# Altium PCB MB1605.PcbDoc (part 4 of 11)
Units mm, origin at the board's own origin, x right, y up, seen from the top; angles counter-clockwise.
Board outline 100 x 79.6 mm, 6 copper layers (Top Layer, Signal Layer 1, Signal Layer 2, Signal Layer 3, Signal Layer 4, Bottom Layer), stack 1.549 mm thick; 644 components, 529 nets, 2853 pads, 1462 vias.
Unrouted connection lines stored in the file: 2.
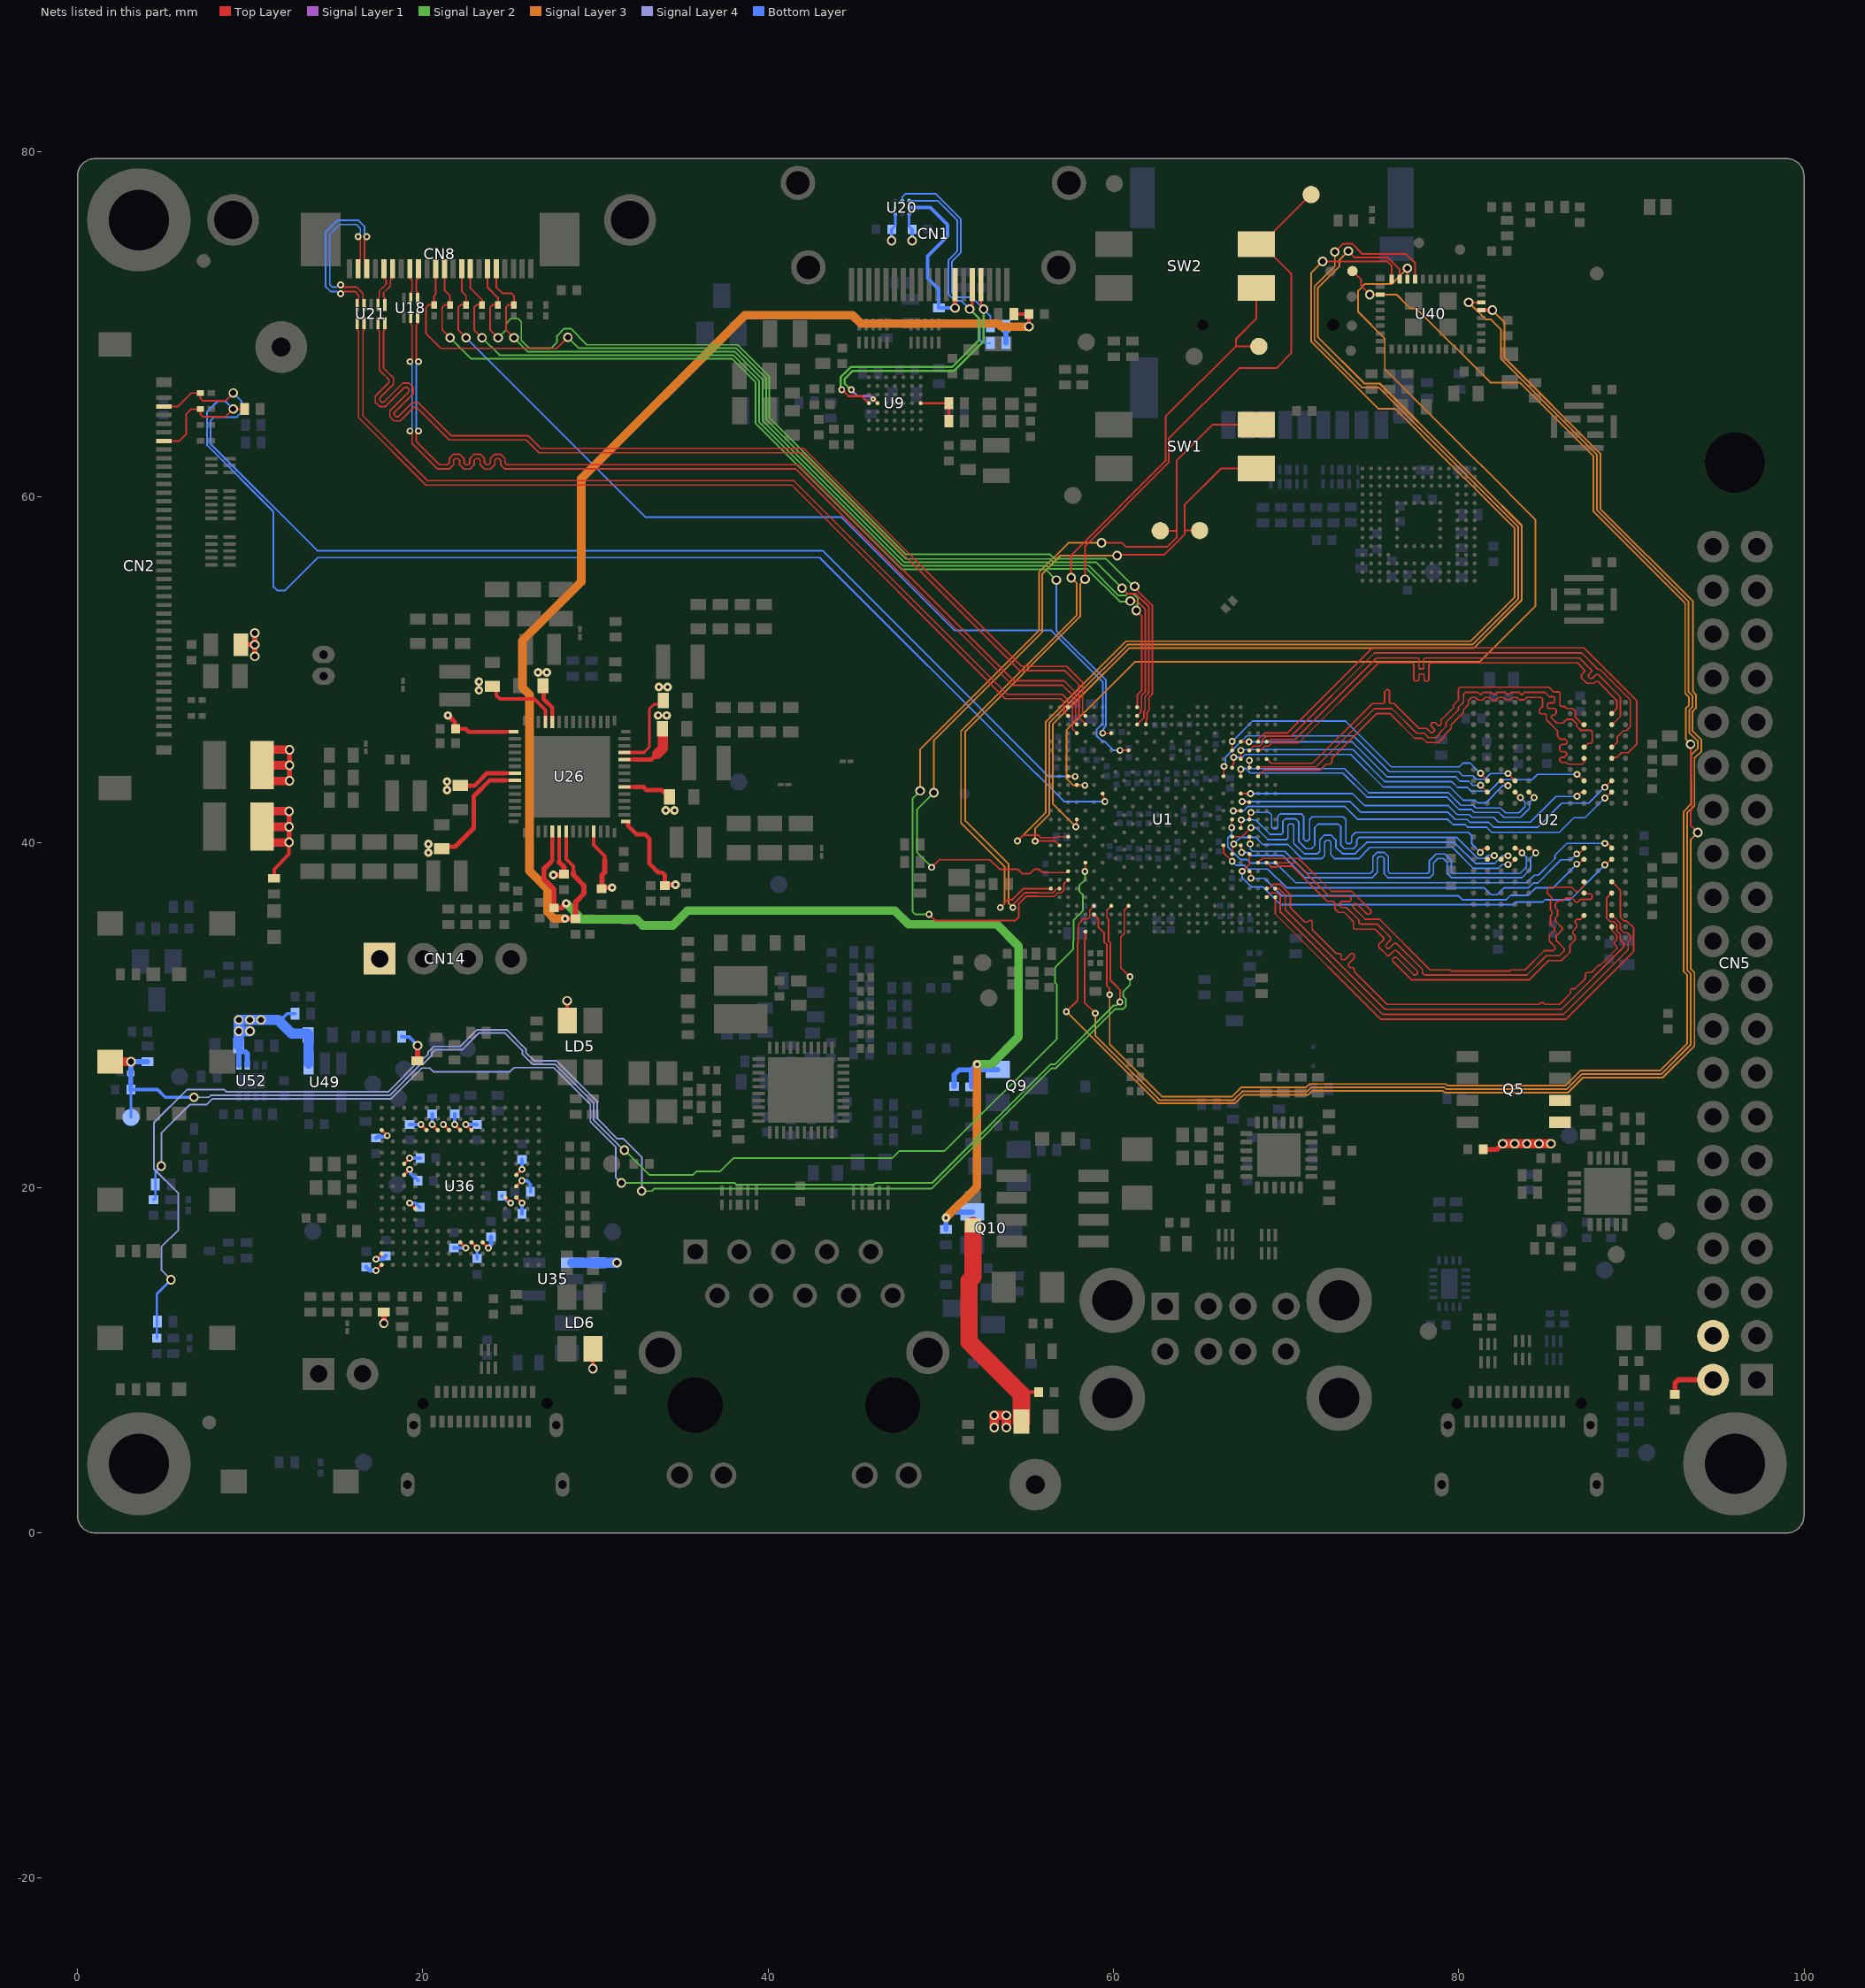
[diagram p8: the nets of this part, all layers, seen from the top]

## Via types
v1: diameter 0.55, hole 0.35, Top Layer to Bottom Layer, 823 vias
v2: diameter 0.4, hole 0.2, Top Layer to Bottom Layer, 235 vias
v3: diameter 0.4, hole 0.2, Top Layer to Bottom Layer, tented both sides, 216 vias
v4: diameter 0.5, hole 0.2, Top Layer to Bottom Layer, 159 vias
v5: diameter 0.25/0.3 (per signal layer), hole 0.1, Top Layer to Signal Layer 1, tented both sides, 29 vias

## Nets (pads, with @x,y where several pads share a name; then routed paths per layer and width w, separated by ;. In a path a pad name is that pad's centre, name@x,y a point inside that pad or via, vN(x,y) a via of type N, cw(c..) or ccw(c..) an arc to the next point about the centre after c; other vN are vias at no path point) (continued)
3V3_STLK: C129.2 C281.1 C282.1 C289.1 C290.1 C297.1 C298.1 C299.1 C303.1 C310.1 C311.1 C324.1 C325.1 C326.1 C327.1 C328.1 C329.1 C333.1 CN14.1 LD5.4 LD6.4 R156.2 R227.1 U35.1 U36.C1 U36.C5 U36.C6 U36.C7 U36.C8 U36.C9 U36.F3 U36.G3 U36.G13 U36.H13 U36.J12 U36.J13 U36.K4 U36.N8 U36.N9 U36.N10 U36.P1 U36.R1 | length 26.9
  Top Layer w0.15: v3(17.29,15.207) U36.R1@17.615,15.532 ; v3(17.29,15.857) U36.P1@17.615,16.182 ; U36.C1@17.615,23.332 v3(17.94,23.007) ; U36.G3@18.915,20.732 v3(19.24,21.057) ; U36.F3@18.915,21.382 v3(19.24,21.707) ; v3(19.24,19.107) U36.K4@19.565,18.782 ; v3(19.89,23.657) U36.C5@20.215,23.332 ; v3(20.54,23.657) U36.C6@20.865,23.332 ; v3(21.19,23.657) U36.C7@21.515,23.332 ; v3(21.84,23.657) U36.C8@22.165,23.332 ; U36.N8@22.165,16.832 v3(22.49,16.507) ; v3(22.49,23.657) U36.C9@22.815,23.332 ; U36.N9@22.815,16.832 v3(23.14,16.507) ; U36.N10@23.465,16.832 v3(23.79,16.507) ; U36.J12@24.765,19.432 v3(25.09,19.107) ; U36.J13@25.415,19.432 v3(25.74,19.107) ; U36.H13@25.415,20.082 v3(25.74,20.407) ; U36.G13@25.415,20.732 v3(25.74,21.057)
  Top Layer w0.2: LD5.4@28.358,29.675 v1(28.358,30.825) ; v1(29.85,9.519) LD6.4@29.85,10.669
  Top Layer w0.3: R156.2@19.69,27.357 19.69,28.215 v1(19.7,28.225)
  Bottom Layer w0.2: R227.1@18.765,28.75 18.792,28.722 19.203,28.722 v1(19.7,28.225) ; v3(19.24,19.107) 19.565,19.107 C299.1@19.815,18.857 ; v3(19.24,21.057) 19.278,21.019 19.278,20.844 19.535,20.587 19.56,20.587 19.715,20.432 C298.1@19.715,20.407 ; v3(19.24,21.707) C310.1@19.84,21.707 ; C289.1@19.24,23.657 v3(19.89,23.657) ; v3(20.54,23.657) C282.1@20.54,24.282 ; C326.1@21.79,16.507 v3(22.49,16.507) ; v3(21.84,23.657) C297.1@21.84,24.282 ; v3(22.49,23.657) C290.1@23.14,23.657 ; C325.1@23.14,15.882 v3(23.14,16.507) ; C329.1@24.59,19.532 24.59,19.507 24.745,19.352 24.77,19.352 24.977,19.145 25.052,19.145 v3(25.09,19.107) ; C303.1@25.74,18.482 v3(25.74,19.107) ; v3(25.74,20.407) 26.02,20.407 26.24,20.187 C328.1@26.24,19.757 ; v3(25.74,21.057) C311.1@25.74,21.632
  Bottom Layer w0.25: C327.1@16.715,15.407 16.915,15.207 v3(17.29,15.207) ; v3(17.29,15.857) 17.665,15.857 C281.1@17.865,16.057 ; C324.1@17.29,22.875 17.367,22.952 17.844,22.952 17.899,23.007 v3(17.94,23.007) ; v3(23.79,16.507) 23.945,16.662 C333.1@23.945,17.157
  Bottom Layer w0.6: U35.1@28.646,15.65 C129.2@30.17,15.65 v1(31.239,15.65)
5V_HDMI: C91.1 C179.2 R20.1 R21.2 R22.2 U26.7 | length 68.5
  Top Layer w0.2: R20.1@54.226,70.6 C179.2@55.103,70.6 ; v1(55.103,69.873) C179.2@55.103,70.6
  Top Layer w0.21: U26.7@28.3,40.63 28.3,39.025 28.715,38.61 28.715,38.253
  Top Layer w0.3: v4(28.24,35.58) C91.1@28.85,35.58 ; 28.715,38.253 28.715,38.118 29.335,37.498 29.335,37.035 28.85,36.55 C91.1@28.85,35.73
  Signal Layer 3 w0.5: v4(28.24,35.58) 27.619,35.58 27.223,35.976 27.223,37.302 26.175,38.35 26.175,48.553 25.769,48.959 25.769,51.68 29.175,55.086 29.175,61.065 38.645,70.534 44.893,70.534 45.378,70.049 53.326,70.049 53.502,69.873 v1(55.103,69.873)
  Bottom Layer w0.3: R22.2@53.776,68.92 R21.2@53.776,69.903 54.424,69.903 54.454,69.873 v1(55.103,69.873)
5V_STLK: C29.2 C30.2 C32.2 C38.2 C39.2 C42.1 C56.2 C94.2 C143.2 C146.2 C147.1 C165.2 C169.2 C180.2 C181.2 C184.2 C188.2 C199.2 C209.2 C213.2 C233.2 CN5.2 CN5.4 L12.1 Q5.5 Q5.6 R4.2 R210.1 R216.2 R230.1 U20.A1 U20.C1 U26.6 U26.11 U26.15 U26.20 U26.24 U26.25 U26.38 U26.39 U26.43 U26.49 U26.50 U49.1 U52.5 U52.6 | length 101.6
  Top Layer w0.15: 32.8,45.2 33.125,45.525 33.125,47.731 33.388,47.994 33.819,47.994 C32.2@33.925,48.1
  Top Layer w0.2: R210.1@11.386,37.915 11.386,38.449 12.244,39.307 v1@12.244,39.994 ; 54.67,8.389 54.899,8.16 C146.2@55.659,8.16
  Top Layer w0.21: C29.2@24.025,49.05 24.262,48.813 24.262,48.513 24.475,48.3 26.464,48.3 27.1,47.664 U26.39@27.1,46.97 ; 24.775,43.6 U26.50@25.33,43.6 ; 24.775,44 U26.49@25.33,44 ; 24.775,46.4 U26.43@25.33,46.4 ; U26.38@27.5,46.97 27.5,47.525 ; 27.9,38.85 U26.6@27.9,40.63 ; U26.11@29.9,40.63 29.9,39.843 30.54,39.203 30.54,38.975 ; U26.15@31.67,41.2 U26.15@31.745,41.2 U26.15@31.785,41.2 ; U26.20@31.67,43.2 32.225,43.2 ; U26.24@31.67,44.8 32.225,44.8 ; U26.25@31.67,45.2 32.8,45.2
  Top Layer w0.25: C56.2@21.1,39.75 21.875,39.75 22.95,40.825 22.95,42.669 23.881,43.6 24.775,43.6 ; 21.695,47.125 21.699,47.125 21.845,46.979 21.845,46.685 C39.2@21.955,46.575 ; C39.2@22.005,46.575 22.475,46.575 22.65,46.4 24.775,46.4 ; C199.2@22.175,43.275 22.991,43.275 23.716,44 24.775,44 ; C30.2@26.925,49.075 26.994,49.006 26.994,48.308 27.5,47.802 27.5,47.525 ; 31.895,41.095 31.895,40.947 32.371,40.472 32.853,40.472 33.125,40.2 33.125,38.759 33.634,38.25 33.879,38.25 34.025,38.104 C188.2@34.025,37.55 ; 32.225,43.2 32.788,43.2 32.963,43.025 33.847,43.025 33.972,42.9 34.05,42.9 34.247,42.703 C184.2@34.247,42.625 ; 32.225,44.8 33.25,44.8 33.575,45.125
  Top Layer w0.3: R4.2@9.464,51.449 v1(10.264,51.449) ; v1(10.264,50.774) v1(10.264,51.449) ; v1(10.264,52.124) v1(10.264,51.449) ; v1(12.25,40) v1(12.25,40.9) v1(12.25,41.8) ; v1(12.275,43.563) v1(12.275,44.463) v1(12.275,45.363) ; v1(17.74,12.137) R216.2@17.74,12.782 ; v4@21.444,47.376 21.695,47.125 ; v4(27.565,38.11) 28.175,38.11 28.174,38.111 28.174,38.576 27.9,38.85 ; C209.2@30.35,37.38 C209.2@30.375,37.38 ; 30.54,38.975 30.54,38.269 30.375,38.104 C209.2@30.375,37.38 ; v4(30.96,37.38) C209.2@30.375,37.38 ; C188.2@34.025,37.55 v4(34.635,37.55) ; C94.2@81.42,22.212 82.218,22.212 v1(82.545,22.539) ; C233.2@92.524,8.02 92.524,8.679 92.715,8.87 CN5.2@94.73,8.87
  Top Layer w0.5: C147.1@10.686,39.994 v1@12.269,39.994 ; C147.1@10.686,40.906 v1@12.269,40.906 ; C147.1@10.686,41.806 v1@12.269,41.806 ; C42.1@10.686,43.557 v1@12.269,43.557 ; C42.1@10.686,44.468 v1@12.269,44.468 ; C42.1@10.686,45.368 v1@12.269,45.368
  Top Layer w0.55: v1(53.095,6.106) v1(53.095,6.806) v1(53.795,6.806) v1(53.795,6.106) ; v1(82.545,22.539) v1(83.245,22.539) v1(83.945,22.539) v1(84.645,22.539) v1(85.345,22.539)
  Top Layer w0.6: 33.575,45.125 33.9,45.45 C38.2@33.9,46.175
  Top Layer w1: L12.1@51.875,17.813 51.875,14.837 51.625,14.587 51.625,11.075 54.67,8.03 C143.2@54.67,6.456
  Bottom Layer w0.15: C180.2@47.152,75.504 47.364,75.716 U20.C1@47.364,76.369 ; U20.A1@48.164,76.369 48.164,75.683 C181.2@48.343,75.504
  Bottom Layer w0.2: 11.695,29.641 12.129,30.075 R230.1@12.592,30.075 ; v1@47.152,74.854 C180.2@47.152,75.504 ; v1@48.343,74.854 C181.2@48.343,75.504
  Bottom Layer w0.3: U52.5@9.336,27.077 C169.2@9.336,28.092 ; C169.2@9.336,28.217 C169.2@9.336,28.092 ; U52.6@9.836,27.077 9.836,27.755 9.719,27.872 9.556,27.872 C169.2@9.336,28.092
  Bottom Layer w0.6: C169.2@9.336,28.217 v1(9.336,29.068) ; v1(9.981,29.068) v1(9.336,29.068) ; C165.2@13.362,28.848 13.362,28.904 13.342,28.924 12.412,28.924 11.695,29.641 11.623,29.713 v1(9.336,29.713) v1(9.336,29.068) ; U49.1@13.381,27.193 C165.2@13.381,28.829
  other v1: 9.981,29.713 10.626,29.713 47.147,74.849 48.338,74.849
  other v4: 20.325,39.4 20.325,39.9 34.075,41.85 34.575,41.85 21.4,43.025 21.4,43.525 21.45,47.348 33.625,47.35 34.125,47.35 23.25,48.8 33.675,49 34.175,49 23.25,49.3 26.675,49.85 27.175,49.85
5V_VCONN: C105.1 C214.1 Q9.2 Q10.2 R8.2 R12.2 U26.5 | length 58.5
  Top Layer w0.21: 27.378,38.827 27.5,38.95 U26.5@27.5,40.63
  Top Layer w0.3: 27.378,38.827 27.01,38.46 27.01,37.865 27.6,37.275 C214.1@27.6,36.2 28.04,36.2 v4(28.3,36.46)
  Signal Layer 2 w0.5: v4(28.3,36.46) 29.21,35.55 32.366,35.55 32.726,35.19 34.474,35.19 35.325,36.041 47.336,36.041 48.124,35.253 53.229,35.253 54.504,33.979 54.504,28.734 52.92,27.15 v4(52.1,27.15)
  Signal Layer 3 w0.5: v4(50.3,18.25) 52.1,20.05 v4(52.1,27.15)
  Bottom Layer w0.3: R12.2@50.297,17.588 50.298,17.589 50.298,18.248 v4(50.3,18.25) 50.638,18.588 Q10.2@51.822,18.588 ; C105.1@50.775,25.85 50.775,26.546 51.054,26.825 51.775,26.825 ; R8.2@51.775,25.838 51.775,26.825 ; Q9.2@53.3,26.838 52.412,26.838 v4(52.1,27.15) 51.775,26.825
BOOT0: SW1.1 TP15.1 U1.Y3 | length 45.8
  Top Layer w0.09: 56.114,38.255 57.267,38.255 57.337,38.325 U1.Y3@57.375,38.325
  Top Layer w0.1: v2(49.475,38.554) 49.913,38.992 50.642,38.992 50.644,38.994 52.847,38.994 53.391,38.45 54.448,38.45 54.704,38.194 55.16,38.194 55.402,38.435 55.695,38.435 55.875,38.255 56.114,38.255 ; v1(60.212,56.607) 60.255,56.65 62.925,56.65 64.136,57.861 64.136,58.075 ; TP15.1@64.995,58.058 64.153,58.058 64.136,58.075 ; SW1.1@68.275,61.655 66.236,61.655 64.136,59.555 64.136,58.075
  Signal Layer 2 w0.1: v2(49.475,38.554) 48.627,39.402 48.627,41.902 v1(49.6,42.875)
  Signal Layer 3 w0.1: v1(49.6,42.875) 49.6,45.92 55.875,52.196 55.875,55.557 56.925,56.607 v1(60.212,56.607)
BOOT1: SW1.2 TP16.1 U1.AA3 | length 53.4
  Top Layer w0.09: 55.625,36.869 56.566,36.869 56.771,37.075 56.979,37.075 57.125,37.221 57.125,37.575 U1.AA3@57.375,37.825
  Top Layer w0.1: v2(49.325,35.825) 49.692,35.458 54.29,35.458 54.527,35.695 54.527,36.453 54.943,36.869 55.625,36.869 ; v1(59.305,57.346) 60.498,57.346 60.735,57.11 63.116,57.11 63.67,57.664 63.67,58.04 ; TP16.1@62.711,58.047 63.664,58.047 63.67,58.04 ; SW1.2@68.275,64.195 65.743,64.195 63.67,62.122 63.67,58.04
  Signal Layer 2 w0.1: v1(48.805,42.984) 48.375,42.555 48.375,35.98 48.53,35.825 v2(49.325,35.825)
  Signal Layer 3 w0.1: v1(48.805,42.984) 48.805,45.394 55.685,52.274 55.685,55.636 57.396,57.346 v1(59.305,57.346)
BOOT2: SW2.1 TP25.1 U1.AB1 | length 49.1
  Top Layer w0.1: v2(53.45,36.225) 53.9,36.675 54.139,36.675 54.789,37.325 U1.AB1@56.375,37.325 ; v1(57.55,55.325) 57.55,56.627 63.02,62.097 63.02,64.654 67.09,68.725 ; SW2.1@68.275,72.105 68.275,70.322 67.09,69.137 67.09,68.725 ; TP25.1@68.425,68.725 67.09,68.725
  Signal Layer 3 w0.1: v2(53.45,36.225) 53.705,36.48 53.705,38.592 51.172,41.125 51.172,46.448 57.88,53.155 57.88,54.995 v1(57.55,55.325)
BOOT3: SW2.2 TP32.1 U1.AB2 | length 57
  Top Layer w0.09: 55.625,37.075 56.479,37.075 56.702,37.298 56.848,37.298 U1.AB2@56.875,37.325
  Top Layer w0.1: v2(54.175,36.225) 54.175,36.384 54.866,37.075 55.625,37.075 ; v1(58.361,55.242) 58.361,57.169 63.21,62.018 63.21,63.402 67.279,67.47 69.439,67.47 70.294,68.325 70.294,72.951 SW2.2@68.6,74.645 ; SW2.2@68.275,74.645 SW2.2@68.6,74.645 ; TP32.1@71.45,77.525 69.3,75.375 69.3,75.345 SW2.2@68.6,74.645
  Signal Layer 3 w0.1: v2(54.175,36.225) 53.935,36.465 53.935,38.729 51.419,41.246 51.419,46.426 58.07,53.077 58.07,54.952 v1(58.361,55.242)
BT_DEV_WAKE: U1.AE6 U40.39 | length 93.9
  Top Layer w0.09: U1.AE6@58.875,35.825 59.125,35.575 59.125,35.104
  Top Layer w0.1: 59.125,35.104 59.454,34.775 59.454,34.234 59.623,34.064 59.623,31.68 59.778,31.525 59.778,31.178 v2(59.781,31.175) ; v1(80.575,71.275) U40.39@81.3,71.275
  Signal Layer 3 w0.1: v2(59.781,31.175) 59.781,28.304 62.808,25.276 66.878,25.276 67.415,25.813 71.169,25.813 71.359,26.003 79.259,26.003 79.357,25.904 86.174,25.904 87.045,26.775 91.658,26.775 93.235,28.352 93.235,32.314 93.03,32.52 93.03,41.786 93.455,42.211 93.455,45.058 93.855,45.457 93.855,45.853 93.35,46.357 93.35,47.664 93.543,47.857 93.543,48.474 93.318,48.699 93.318,53.929 88.008,59.239 88.008,62.443 82.45,68 82.45,69.7 81.85,70.3 81.551,70.3 v1(80.575,71.275)
BT_HOST_WAKE: U1.AG5 U40.38 | length 92.5
  Top Layer w0.1: U1.AG5@58.375,34.825 58.375,34.404 58.325,34.354 58.325,33.533 58.325,30.725 v2(58.95,30.1)
  Top Layer w0.2: U40.38@81.3,70.825 v1(81.95,70.825)
  Signal Layer 3 w0.1: v2(58.95,30.1) 58.95,28.799 62.673,25.076 66.961,25.076 67.46,25.575 71.215,25.575 71.442,25.803 79.176,25.803 79.274,25.704 86.257,25.704 87.128,26.575 91.741,26.575 93.435,28.269 93.435,32.397 93.23,32.603 93.23,41.703 93.655,42.128 93.655,44.875 94.055,45.275 94.055,45.936 93.55,46.44 93.55,47.581 93.743,47.774 93.743,48.557 93.572,48.728 93.572,53.958 88.208,59.322 88.208,62.526 82.65,68.083 82.65,70.125 v1(81.95,70.825)
BT_PCM_CLK: U1.T3 U40.11 | length 71
  Top Layer w0.09: 55.625,40.42 55.648,40.42 55.793,40.275 56.68,40.275 56.73,40.325 U1.T3@57.375,40.325
  Top Layer w0.1: v2(54.436,40.077) 54.779,40.42 55.625,40.42 ; v1(72.125,73.65) 75.848,73.65 76.125,73.373 U40.11@76.125,72.625
  Signal Layer 3 w0.1: v2(54.436,40.077) 56.089,41.729 56.089,46.998 57.666,48.575 60.741,51.65 80.699,51.65 83.25,54.201 83.25,58.175 81.346,60.079 79.316,62.109 76.3,65.125 75.34,65.125 71.445,69.02 71.445,72.97 v1(72.125,73.65)
BT_PCM_SDI: U1.P4 U40.10 | length 67.4
  Top Layer w0.1: v3(57.819,40.906) 57.869,41.277 U1.P4@57.875,41.325 ; v1(73.6,74.25) 73.975,73.875 75.906,73.875 76.575,73.206 U40.10@76.575,72.625
  Signal Layer 3 w0.1: v3(57.819,40.906) 56.479,42.246 56.479,46.822 58.232,48.575 60.907,51.25 80.864,51.25 83.65,54.036 83.65,58.35 81.346,60.654 79.891,62.109 75.425,66.575 74.531,66.575 71.845,69.261 71.845,72.124 73.1,73.379 73.1,73.75 v1(73.6,74.25)
BT_PCM_SDO: U1.K4 U40.9 | length 61.2
  Top Layer w0.1: U1.K4@57.875,43.325 v3(58.348,43.3) ; U40.9@77.025,72.625 v1(77.025,73.25)
  Signal Layer 3 w0.1: v3(58.348,43.3) 57.675,43.3 57.279,43.697 57.279,46.49 59.363,48.575 61.238,50.45 81.196,50.45 84.45,53.704 84.45,58.681 81.346,61.785 81.023,62.109 75.719,67.413 75.719,69.182 74.175,70.726 74.175,71.951 74.574,72.35 76.125,72.35 v1(77.025,73.25)
BT_PCM_WS: U1.U2 U40.8 | length 71.1
  Top Layer w0.09: v2@55.625,40.075 56.625,40.075 U1.U2@56.875,39.825
  Top Layer w0.1: v2(55.458,40.07) 55.463,40.075 v2@55.625,40.075 ; v1(72.825,74.2) 73.3,74.675 73.825,74.675 74.425,74.075 76.955,74.075 77.475,73.555 U40.8@77.475,72.625
  Signal Layer 3 w0.1: v2(55.458,40.07) 55.458,40.792 55.625,40.958 56.279,41.612 56.279,46.905 57.949,48.575 60.824,51.45 80.781,51.45 83.45,54.119 83.45,58.267 81.346,60.371 79.608,62.109 75.367,66.35 74.398,66.35 71.645,69.103 71.645,72.207 72.825,73.387 v1(72.825,74.2)
BT_REG_ON: TP19.1 U1.AD6 U40.14 | length 103.4
  Top Layer w0.09: 57.925,34.075 57.925,34.16 57.945,34.18 57.945,35.003 57.985,35.043 57.985,35.289 58.271,35.575 58.525,35.575 58.625,35.675 58.625,36.075 U1.AD6@58.875,36.325
  Top Layer w0.1: v2(57.271,30.195) 57.925,30.848 57.925,34.075 ; TP19.1@73.844,73.087 74.355,72.576 74.355,72.22 v1(74.85,71.725) U40.14@75.45,71.725 ; v1(93.43,45.677) 93.43,43.707 93.501,43.635 93.501,41.873 93.43,41.801 93.43,40.983 v1(93.85,40.562)
  Signal Layer 2 w0.1: v1(93.43,45.677) v1@93.43,45.739
  Signal Layer 3 w0.1: v2(57.271,30.195) 62.59,24.876 67.044,24.876 67.543,25.375 71.297,25.375 71.525,25.603 79.093,25.603 79.191,25.504 86.34,25.504 87.21,26.375 91.824,26.375 93.655,28.206 93.655,32.46 93.43,32.685 93.43,40.142 v1(93.85,40.562) ; v1(74.85,71.725) 76.401,71.725 76.95,71.176 76.95,71.174 77.199,70.925 77.55,70.925 81.84,66.634 83.533,66.634 87.808,62.36 87.808,59.156 93.118,53.846 93.118,48.616 93.343,48.391 93.343,47.939 93.15,47.747 93.15,45.998 93.43,45.719 v1(93.43,45.677)
BUTTON.TAMP: B3.1 C163.2 R139.1 TP6.1 U1.W5 U28.1 | length 79.4
  Top Layer w0.09: v3(58.349,38.315) 58.375,38.341 U1.W5@58.375,38.825
  Top Layer w0.5: B3.1@1.886,27.3 v1(3.095,27.3)
  Signal Layer 2 w0.1: v1(31.672,22.174) 33.109,20.737 35.646,20.737 35.846,20.937 37.214,20.937 37.977,21.7 47.184,21.7 47.609,22.125 50.22,22.125 56.721,28.626 56.721,31.773 56.606,31.888 56.606,32.744 57.675,33.813 57.675,34.075 57.675,34.272 57.685,34.282 57.685,35.49 58.225,36.03 58.225,36.97 58.025,37.17 58.025,37.495 58.349,37.819 v3(58.349,38.315)
  Signal Layer 4 w0.1: v1(6.742,25.232) 7.6,25.232 7.71,25.342 18.066,25.342 19.901,27.177 20.032,27.177 20.515,27.66 20.515,27.791 20.703,27.98 22.262,27.98 23.232,28.95 24.768,28.95 25.765,27.952 25.765,27.74 26.355,27.15 27.303,27.15 27.655,27.15 29.9,24.905 29.9,24.553 29.9,23.908 31.635,22.174 v1(31.672,22.174)
  Bottom Layer w0.15: TP6.1@3.095,24.07 C163.2@3.095,25.66
  Bottom Layer w0.2: C163.2@3.083,25.673 4.637,25.673 5.078,25.232 v1(6.742,25.232)
  Bottom Layer w0.3: C163.2@3.095,25.66 C163.2@3.083,25.673 U28.1@3.083,26.627 3.095,26.639 v1(3.095,27.3) R139.1@4.056,27.3
BUTTON.USER1: C162.2 R127.1 U1.AD10 | length 89.4
  Top Layer w0.09: 60.473,34.569 60.625,34.721 60.625,36.075 U1.AD10@60.875,36.325
  Top Layer w0.1: 60.473,34.569 60.423,34.52 60.423,32.746 v2(60.96,32.21)
  Signal Layer 2 w0.1: v1(32.675,19.8) 33.261,19.8 33.398,19.937 49.447,19.937 56.422,26.912 56.669,26.912 60.106,30.35 60.575,30.35 60.725,30.5 60.725,30.915 60.575,31.065 60.575,31.345 60.96,31.73 v2(60.96,32.21)
  Signal Layer 4 w0.1: v1(5.413,14.669) 4.85,15.231 4.85,16.561 5.838,17.549 5.838,19.663 4.425,21.076 4.425,23.762 6.336,25.673 8.506,25.673 8.627,25.552 17.993,25.552 19.818,27.377 19.949,27.377 20.315,27.743 20.315,27.874 20.621,28.18 22.179,28.18 23.149,29.15 24.85,29.15 25.965,28.035 25.965,27.823 26.438,27.35 27.385,27.35 27.737,27.35 30.1,24.987 30.1,24.635 30.1,23.991 31.265,22.826 31.621,22.826 32.675,21.772 v1(32.675,19.8)
  Bottom Layer w0.15: C162.2@4.592,11.287 R127.1@4.592,12.197 ; R127.1@4.632,12.237 R127.1@4.592,12.197 ; v1(5.413,14.669) 4.592,13.848 R127.1@4.592,12.197
BUTTON.USER2: C161.2 R126.1 U1.AD8 | length 76.1
  Top Layer w0.09: 59.625,35.629 59.625,36.075 U1.AD8@59.875,36.325
  Top Layer w0.1: 59.625,35.629 59.729,35.525 59.729,34.27 59.823,34.176 59.823,32.01 60.395,31.439 60.395,30.77 v2(60.375,30.75)
  Signal Layer 2 w0.1: v1(31.5,20.275) 38.048,20.275 38.149,20.174 46.121,20.174 46.222,20.275 49.502,20.275 56.377,27.15 56.623,27.15 60.023,30.55 60.166,30.55 60.366,30.75 v2(60.375,30.75)
  Signal Layer 4 w0.1: v1(4.85,21.252) 4.85,23.157 6.5,24.807 7.457,24.807 7.793,25.142 18.149,25.142 19.931,26.925 20.396,26.925 20.614,26.707 25.041,26.707 25.284,26.95 27.572,26.95 29.7,24.822 29.7,23.825 31.172,22.353 31.172,20.603 v1(31.5,20.275)
  Bottom Layer w0.15: C161.2@4.406,19.3 4.513,19.406 R126.1@4.513,20.187 4.513,20.915 v1(4.85,21.252)
CAM.EN: CN8.18 U1.A11 U33.1 | length 55.7
  Top Layer w0.1: CN8.18@24.25,73.222 24.25,72.158 24.604,71.804 25.129,71.804 25.275,71.658 U33.1@25.275,71.126 24.959,71.126 24.817,70.984 24.817,69.688 v1(25.28,69.226) ; v1(61.325,53.425) 61.637,53.113 61.637,48.792 61.375,48.53 U1.A11@61.375,47.825
  Signal Layer 2 w0.1: v1(25.28,69.226) 26.089,68.416 38.068,68.416 39.677,66.807 39.677,64.427 47.889,56.215 56.232,56.215 56.416,56.031 58.568,56.031 60.299,54.3 60.699,54.3 60.799,54.4 61.151,54.4 61.4,54.151 61.4,53.799 61.377,53.776 61.377,53.477 v1(61.325,53.425)
CAM.IMU_INT1: CN8.14 U1.F10 U31.1 | length 55.3
  Top Layer w0.1: CN8.14@22.25,73.222 22.25,71.908 22.5,71.658 U31.1@22.5,71.126 22.184,71.126 22.042,70.984 22.042,69.688 v1(22.505,69.226) ; v3(60.375,45.325) U1.F10@60.875,45.325
  Bottom Layer w0.1: v1(22.505,69.226) 32.885,58.845 44.234,58.845 50.806,52.273 56.407,52.273 59.375,49.305 59.375,48.575 59.375,46.875 59.025,46.525 59.025,46.18 59.355,45.85 59.478,45.85 60.003,45.325 v3(60.375,45.325)
CAM.IMU_INT2: CN8.15 U1.B11 U14.1 | length 57.6
  Top Layer w0.09: U1.B11@61.375,47.325 61.585,47.535 61.585,47.681 61.625,47.721 61.625,48.504 61.85,48.729 61.85,48.875
  Top Layer w0.1: CN8.15@22.75,73.222 22.75,72.095 23.425,71.42 U14.1@23.425,71.126 23.109,71.126 22.967,70.984 22.967,69.688 v1(23.43,69.226) ; v1(60.975,53.975) 60.988,53.962 61.389,53.962 61.85,53.501 61.85,48.875
  Signal Layer 2 w0.1: v1(23.43,69.226) 24.439,68.216 37.985,68.216 39.477,66.724 39.477,64.344 47.807,56.015 56.149,56.015 56.333,55.831 58.485,55.831 60.366,53.95 60.95,53.95 v1(60.975,53.975)
CAM.RST: CN8.17 U1.C12 U32.1 | length 60.5
  Top Layer w0.09: U1.C12@61.88,46.83 61.895,46.845 61.895,47.09 61.945,47.14 61.945,47.532 62.065,47.652 62.065,48.407 62.233,48.575
  Top Layer w0.1: CN8.17@23.75,73.222 23.75,72.135 24.35,71.535 U32.1@24.35,71.126 24.034,71.126 23.892,70.984 23.892,69.688 v1(24.355,69.226) ; v1(61.225,54.825) 61.225,54.759 62.25,53.734 62.25,48.594 62.233,48.577 62.233,48.575
  Signal Layer 2 w0.1: v1(24.355,69.226) 24.826,69.697 24.826,70.021 24.85,70.045 24.85,70.079 25.099,70.328 25.521,70.328 25.705,70.144 25.705,69.083 26.172,68.616 27.422,68.616 27.775,68.969 27.775,69.334 28.198,69.757 28.568,69.757 29.507,68.818 38.232,68.818 40.077,66.973 40.077,64.593 47.99,56.68 56.334,56.68 56.583,56.431 59.563,56.431 61.169,54.825 v1(61.225,54.825)
CAM.TOF_INT: CN8.12 U1.D8 U29.1 | length 57.7
  Top Layer w0.09: v3(59.375,46.325) U1.D8@59.875,46.325
  Top Layer w0.1: CN8.12@21.25,73.222 21.25,71.983 21.575,71.658 U29.1@21.575,71.126 21.259,71.126 21.117,70.984 21.117,69.688 v1(21.58,69.226)
  Signal Layer 2 w0.1: v1(21.58,69.226) 22.789,68.016 37.902,68.016 39.277,66.641 39.277,64.262 47.724,55.815 56.066,55.815 v1(56.69,55.191)
  Bottom Layer w0.1: v1(56.69,55.191) 56.69,52.273 59.575,49.388 59.575,48.575 59.575,46.75 59.41,46.585 59.41,46.36 v3(59.375,46.325)
CAM.TOF_LPn: CN8.11 U1.C11 U11.1 | length 61.6
  Top Layer w0.09: U1.C11@61.375,46.825 61.765,47.215 61.765,47.607 61.826,47.668 61.826,48.429 61.972,48.575
  Top Layer w0.1: CN8.11@20.75,73.222 20.75,71.758 20.65,71.658 U11.1@20.65,71.126 20.334,71.126 20.192,70.984 20.192,69.458 21.038,68.612 27.762,68.612 v1(28.4,69.25) ; v1(60.5,54.725) 60.825,54.4 61.301,54.4 62.05,53.651 62.05,48.677 62.045,48.672 62.045,48.648 61.972,48.575
  Signal Layer 2 w0.1: v1(28.4,69.25) 29.032,68.618 38.149,68.618 39.877,66.89 39.877,64.51 47.972,56.415 56.315,56.415 56.499,56.231 58.994,56.231 v1(60.5,54.725)
CEC: CN1.13 R63.1 U20.A2 | length 10.5
  Top Layer w0.25: v1(50.826,70.95) CN1.13@50.826,72.3
  Bottom Layer w0.2: U20.A2@48.164,76.769 49.388,76.769 50.389,75.768 50.389,75.113 49.239,73.964 49.239,72.686 49.889,72.036 R63.1@49.889,70.95 v1(50.826,70.95)
CEC_CLK: R26.2 R30.1 U9.D7 | length 2.7
  Top Layer w0.15: U9.D7@48.836,65.435 R26.2@50.476,65.435 R30.1@50.476,64.395
CSI.CK_N: U1.D4 U18.5 | length 56.6
  Top Layer w0.09: v2(19.25,63.824) 19.375,63.699 19.375,63.106 20.854,61.627 21.315,61.627 21.537,61.627 21.787,61.877 21.787,62.126 21.89,62.229 22.027,62.229 22.131,62.126 22.131,61.867 22.38,61.617 22.725,61.617 22.975,61.867 22.975,62.126 23.078,62.229 23.215,62.229 23.319,62.126 23.319,61.867 23.568,61.617 23.913,61.617 24.163,61.867 24.163,62.126 24.266,62.229 24.403,62.229 24.507,62.126 24.507,61.877 24.756,61.627 25.695,61.627 41.622,61.627 54.147,49.101 57.05,49.101 57.625,48.526 57.625,46.575 U1.D4@57.875,46.325 ; v2(19.25,67.841) 19.375,67.966 19.375,69.955 19.3,70.03 U18.5@19.3,70.425
  Bottom Layer w0.09: v2(19.25,63.824) 19.375,63.949 19.375,67.716 v2(19.25,67.841)
CSI.CK_P: U1.C4 U18.6 | length 55.9
  Top Layer w0.09: U18.6@19.7,70.425 19.7,70.03 19.625,69.955 19.625,67.966 v2(19.75,67.841) ; v2(19.75,63.824) 19.625,63.699 19.625,63.21 20.958,61.877 21.315,61.877 21.433,61.877 21.537,61.98 21.537,62.23 21.786,62.479 22.131,62.479 22.381,62.23 22.381,61.97 22.484,61.867 22.621,61.867 22.725,61.97 22.725,62.23 22.974,62.479 23.319,62.479 23.569,62.23 23.569,61.97 23.672,61.867 23.809,61.867 23.913,61.97 23.913,62.23 24.162,62.479 24.507,62.479 24.757,62.23 24.757,61.98 24.86,61.877 25.695,61.877 41.725,61.877 54.251,49.351 57.153,49.351 57.815,48.69 57.815,47.025 57.859,46.879 U1.C4@57.875,46.825
  Bottom Layer w0.09: v2(19.75,63.824) 19.625,63.949 19.625,67.716 v2(19.75,67.841)
CSI.CKcon_N: CN8.8 U18.2 | length 1.8
  Top Layer w0.09: CN8.8@19.25,73.222 19.25,72.677 19.375,72.552 19.375,71.945 19.3,71.87 U18.2@19.3,71.475
CSI.CKcon_P: CN8.9 U18.1 | length 1.8
  Top Layer w0.09: U18.1@19.7,71.475 19.7,71.87 19.625,71.945 19.625,72.552 19.75,72.677 CN8.9@19.75,73.222
CSI.D0_N: U1.A3 U21.7 | length 53.5
  Top Layer w0.09: U21.7@16.6,70.075 16.6,69.68 16.525,69.605 16.525,68.675 16.525,67.675 16.525,64.704 20.282,60.947 41.476,60.947 53.848,48.575 57.045,48.575 57.355,48.265 57.355,48.052 57.375,48.032 U1.A3@57.375,47.825
CSI.D0_P: U1.B3 U21.6 | length 54.1
  Top Layer w0.09: U21.6@16.2,70.075 16.2,69.68 16.275,69.605 16.275,64.6 20.178,60.697 41.372,60.697 53.744,48.325 56.941,48.325 57.105,48.161 57.105,47.949 57.125,47.929 57.125,47.575 57.373,47.327 U1.B3@57.375,47.327
CSI.D0con_N: CN8.2 U21.4 | length 10.5
  Top Layer w0.09: v3(15.23,72.283) 15.23,72.226 15.298,72.158 16.166,72.158 16.525,71.799 16.525,71.483 16.545,71.463 16.545,71.18 U21.4@16.6,71.125 ; CN8.2@16.25,73.222 16.355,73.327 16.355,73.76 16.375,73.78 16.375,74.922 16.25,75.047 v3(16.25,75.075)
  Bottom Layer w0.09: v3(15.23,72.283) 15.147,72.283 15.022,72.158 14.754,72.158 14.612,72.299 14.612,75.212 15.184,75.784 16.141,75.784 16.375,75.55 16.375,75.357 16.375,75.283 16.25,75.158 v3(16.25,75.075)
CSI.D0con_P: CN8.3 U21.5 | length 11.3
  Top Layer w0.09: v3(15.23,71.783) 15.23,71.84 15.298,71.908 16.062,71.908 16.275,71.695 16.275,71.483 16.255,71.463 16.255,71.18 U21.5@16.2,71.125 ; CN8.3@16.75,73.222 16.645,73.327 16.645,73.76 16.625,73.78 16.625,74.922 16.75,75.047 v3(16.75,75.075)
  Bottom Layer w0.09: v3(15.23,71.783) 15.147,71.783 15.022,71.908 14.65,71.908 14.362,72.196 14.362,75.316 15.08,76.034 16.245,76.034 16.625,75.654 16.625,75.461 16.625,75.283 16.75,75.158 v3(16.75,75.075)
CSI.D1_N: U1.C5 U21.9 | length 59.2
  Top Layer w0.09: U21.9@17.4,70.075 17.4,69.68 17.475,69.605 17.475,67.36 17.663,67.173 17.746,67.089 18.047,66.788 18.047,66.642 17.25,65.846 17.25,65.493 17.494,65.249 17.847,65.249 18.949,66.351 19.095,66.351 19.192,66.253 19.192,66.107 18.09,65.006 18.09,64.653 18.334,64.409 18.687,64.409 19.484,65.206 19.63,65.206 19.64,65.195 19.713,65.122 21.53,63.305 25.993,63.305 26.731,62.567 41.962,62.567 54.586,49.943 57.188,49.943 58.005,49.126 58.005,47.232 58.375,46.862 U1.C5@58.375,46.825
CSI.D1_P: U1.B5 U21.10 | length 58.6
  Top Layer w0.09: U21.10@17.8,70.075 17.8,69.68 17.725,69.605 17.725,67.464 17.839,67.35 17.923,67.266 18.297,66.892 18.297,66.539 17.5,65.742 17.5,65.596 17.598,65.499 17.744,65.499 18.845,66.601 19.198,66.601 19.442,66.357 19.442,66.004 18.34,64.902 18.34,64.756 18.438,64.659 18.584,64.659 19.38,65.456 19.733,65.456 19.807,65.382 19.89,65.299 21.634,63.555 26.097,63.555 26.835,62.817 42.065,62.817 54.689,50.193 57.291,50.193 58.225,49.259 58.225,47.478 58.375,47.328 U1.B5@58.375,47.325
CSI.D1con_N: CN8.5 U21.2 | length 2.3
  Top Layer w0.09: U21.2@17.4,71.125 17.4,71.52 17.475,71.595 17.475,71.929 17.875,72.329 17.875,72.552 17.75,72.677 CN8.5@17.75,73.222
CSI.D1con_P: CN8.6 U21.1 | length 2.3
  Top Layer w0.09: U21.1@17.8,71.125 17.8,71.52 17.725,71.595 17.725,71.825 18.125,72.225 18.125,72.552 18.25,72.677 CN8.6@18.25,73.222
CTP.INT: CN2.2 U1.J3 U4.1 | length 68
  Top Layer w0.1: CN2.2@5,65.25 5.81,65.25 6.585,66.025 U4.1@7.117,66.025 7.117,65.709 7.259,65.567 8.554,65.567 v1(9.017,66.03) v1@9.022,66.025 ; U1.J3@57.375,43.825 57.77,43.825 v3(57.782,43.813)
  Bottom Layer w0.1: v1(9.017,66.03) 9.487,65.559 9.487,64.9 9.225,64.638 7.916,64.638 7.712,64.434 7.712,63.065 13.885,56.893 43.153,56.893 55.625,44.421 56.233,43.813 v3(57.782,43.813)
CTP.RST: CN2.6 R3.2 U1.L7 U7.1 | length 75.7
  Top Layer w0.1: CN2.6@5,63.25 5.887,63.25 6.29,63.653 6.29,64.805 6.585,65.1 U7.1@7.117,65.1 7.117,64.784 7.259,64.642 8.554,64.642 v1(9.017,65.105) 9.022,65.1 R3.2@9.674,65.1 ; U1.L7@59.375,42.825 v3(59.505,42.369)
  Bottom Layer w0.1: v1(9.017,65.105) 8.572,65.55 8.113,65.55 7.5,64.937 7.5,62.995 11.35,59.145 11.35,54.8 11.575,54.575 12,54.575 13.918,56.493 42.987,56.493 55.528,43.952 55.551,43.952 55.625,43.878 57.134,42.369 v3(59.505,42.369)
DDC_SCL: CN1.15 R22.1 U9.D1 U20.A3 | length 27.1
  Top Layer w0.13: v2(44.259,66.212) 44.3,66.212 44.665,65.846 45.425,65.846 U9.D1@45.836,65.435
  Top Layer w0.15: v1(51.676,70.888) 51.676,70.996 51.826,71.146 CN1.15@51.826,72.3
  Signal Layer 2 w0.13: v2(44.259,66.212) 44.211,66.259 44.211,66.958 44.782,67.53 50.661,67.53 52.208,69.077 52.208,70.355 v1(51.676,70.888)
  Bottom Layer w0.1: U20.A3@48.164,77.169 49.816,77.169 50.953,76.032 50.953,74.233 50.453,73.733 50.453,71.74 50.817,71.375 51.185,71.375 v1@51.672,70.888 ; v1(51.676,70.888) 52.262,70.301 52.262,69.112 52.453,68.92 R22.1@52.876,68.92
DDC_SDA: CN1.16 R21.1 U9.D2 U20.B3 | length 27.1
  Top Layer w0.13: v5(46.086,65.685) U9.D2@46.336,65.435
  Top Layer w0.15: CN1.16@52.326,72.3 52.326,71.146 52.476,70.996 v1(52.476,70.888)
  Signal Layer 1 w0.13: v2(44.816,66.211) 44.816,66.206 45.169,65.853 45.918,65.853 v5(46.086,65.685)
  Signal Layer 2 w0.13: v2(44.816,66.211) 44.79,66.211 44.44,66.561 44.44,66.863 44.877,67.3 50.756,67.3 52.476,69.02 v1(52.476,70.888)
  Bottom Layer w0.1: U20.B3@47.764,77.169 47.764,77.375 47.965,77.576 49.692,77.576 51.153,76.115 51.153,74.15 50.653,73.65 50.653,71.822 50.9,71.575 51.788,71.575 v1(52.476,70.888) 52.876,70.488 R21.1@52.876,69.903
DDR_CA0_A: U1.V24 U2.H2 | length 24.7
  Top Layer w0.09: v3(67.46,38.325) 67.46,38.327 67.875,38.742 U1.V24@67.875,39.325 ; v2(88.46,38.69) 88.497,38.69 88.814,39.007 U2.H2@88.873,39.007
  Bottom Layer w0.09: v3@67.462,38.323 67.462,37.94 67.982,37.42 68.648,37.42 69.677,36.39 83.17,36.39 83.325,36.545 84.879,36.545 85.006,36.672 86.446,36.672 v2@88.46,38.686
DDR_CA0_B: U1.M24 U2.R2 | length 23.5
  Top Layer w0.09: v3(67.46,42.365) 67.5,42.325 U1.M24@67.875,42.325 ; v2@88.472,43.19 88.826,43.544 U2.R2@88.859,43.544
  Bottom Layer w0.09: v3(67.46,42.365) 73.699,42.365 74.313,41.751 79.357,41.751 79.79,41.319 80.495,41.319 80.653,41.16 81.745,41.16 82.03,40.875 84.58,40.875 85.972,42.267 87.537,42.267 v2(88.46,43.19)
DDR_CA1_A: U1.P22 U2.J2 | length 26
  Top Layer w0.09: v3(66.85,40.85) 66.85,41.3 U1.P22@66.875,41.325 ; v2(88.46,39.94) 88.518,39.881 88.689,39.881 88.86,39.71 U2.J2@88.86,39.665
  Bottom Layer w0.09: v3@66.85,40.875 v3(66.85,40.85) 66.85,40.485 66.62,40.255 66.62,39.727 67.337,39.01 67.739,39.01 67.953,38.796 69.42,38.796 70.556,37.66 83.929,37.66 84.37,38.101 84.617,38.101 85.571,39.055 85.571,39.254 86.262,39.945 v2@88.459,39.945
DDR_CA1_B: U1.N23 U2.P2 | length 24
  Top Layer w0.09: v3(66.95,41.825) U1.N23@67.375,41.825 ; v2(88.46,42.565) 88.483,42.565 88.833,42.915 U2.P2@88.86,42.915
  Bottom Layer w0.09: v3(66.95,41.825) 67.536,41.825 67.786,42.075 73.408,42.075 74.152,41.331 79.366,41.331 79.668,41.029 80.373,41.029 80.532,40.87 81.623,40.87 81.908,40.585 85.825,40.585 86.67,41.43 87.314,41.43 88.449,42.565 v2(88.46,42.565)
DDR_CA2_A: U1.V22 U2.H9 | length 20.3
  Top Layer w0.09: U1.V22@66.875,39.325 66.902,39.352 66.902,39.777 v3@66.95,39.825 ; v2@82.859,38.719 82.913,38.774 83.019,38.774 U2.H9@83.26,39.015
  Bottom Layer w0.09: v3(66.965,39.9) 67.357,40.292 68.229,40.292 68.646,39.874 70.103,39.874 70.925,39.051 72.052,39.051 72.238,39.237 72.238,40.022 72.338,40.122 72.5,40.122 72.594,40.029 72.594,39.286 72.829,39.051 74.199,39.051 74.857,39.71 79.632,39.71 80.852,38.49 82.287,38.49 82.51,38.713 v2@82.859,38.713
  other v2: 82.86,38.715
DDR_CA2_B: U1.J21 U2.R9 | length 19.8
  Top Layer w0.09: U1.J21@66.375,43.825 66.387,43.837 66.387,44.388 v3(66.4,44.4) ; v2(82.86,43.99) 82.86,43.977 83.26,43.577 U2.R9@83.26,43.565
  Bottom Layer w0.09: v3(66.4,44.4) 66.4,44.484 66.493,44.577 66.493,44.946 67.712,46.165 73.897,46.165 75.973,44.089 79.989,44.089 80.216,43.862 80.816,43.862 81.018,43.66 81.513,43.66 81.845,43.993 v2@82.857,43.993
DDR_CA3_A: U1.T22 U2.H10 | length 21.6
  Top Layer w0.09: U1.T22@66.875,40.325 67.433,40.325 v3(67.961,40.853) ; U2.H10@82.467,39.008 82.625,39.166 82.801,39.166 v2(82.86,39.225)
  Bottom Layer w0.09: v3(67.961,40.853) 68.252,40.854 68.942,40.164 70.014,40.164 70.103,40.253 70.103,40.98 70.194,41.071 70.355,41.071 70.442,40.983 70.442,39.944 71.045,39.341 71.815,39.341 71.948,39.474 71.948,40.143 72.218,40.412 72.62,40.412 72.884,40.149 72.884,39.711 73.254,39.341 74.012,39.341 74.67,40 79.752,40 80.972,38.78 82.088,38.78 82.533,39.225 v2(82.86,39.225)
DDR_CA3_B: U1.H22 U2.R10 | length 18.7
  Top Layer w0.09: U1.H22@66.875,44.325 66.9,44.35 66.9,44.496 66.975,44.571 66.975,44.918 v3(66.971,44.921) ; U2.R10@82.46,43.565 82.514,43.565 82.789,43.29 v2(82.86,43.29)
  Bottom Layer w0.09: v3(66.971,44.921) 67.47,44.921 67.634,45.085 73.747,45.085 75.627,43.205 79.487,43.205 80.254,42.439 80.959,42.439 81.117,42.28 81.558,42.28 82.568,43.29 v2(82.86,43.29)
DDR_CA4_A: U1.R23 U2.H11 | length 21.6
  Top Layer w0.09: U1.R23@67.375,40.825 67.388,40.838 67.388,41.287 v3(67.4,41.3) ; U2.H11@81.66,39.015 81.714,39.015 81.882,39.183 82.003,39.183 v2(82.06,39.24)
  Bottom Layer w0.09: v3@67.405,41.295 68.245,41.295 69.071,40.47 69.735,40.47 69.813,40.548 69.813,41.214 69.961,41.361 70.568,41.361 70.732,41.197 70.732,40.065 71.165,39.631 71.465,39.631 71.658,39.824 71.658,40.863 71.848,41.053 73.03,41.053 73.174,40.909 73.174,39.832 73.374,39.631 73.891,39.631 74.092,39.832 74.092,40.141 74.24,40.29 79.872,40.29 81.092,39.07 81.511,39.07 81.685,39.244 v2@82.056,39.244
DDR_CA4_B: U1.F22 U2.R11 | length 17.4
  Top Layer w0.09: U1.F22@66.875,45.325 v3(66.875,45.841) ; v2@81.26,43.99 81.66,43.59 U2.R11@81.66,43.565
  Bottom Layer w0.09: v3(66.875,45.841) 68.059,47.025 73.447,47.025 76.093,44.379 80.026,44.379 ; 80.043,44.384 80.248,44.589 80.664,44.589 v2@81.258,43.995
  other v2: 81.26,44.005
DDR_CA5_A: U1.P24 U2.J11 | length 21.1
  Top Layer w0.09: U1.P24@67.875,41.325 67.895,41.345 67.895,41.571 67.97,41.646 v3(67.97,41.73) ; v2@81.235,39.415 81.461,39.641 81.636,39.641 U2.J11@81.66,39.665
  Bottom Layer w0.09: v3(67.97,41.73) 69.015,41.73 69.154,41.591 69.154,40.893 69.256,40.791 69.443,40.791 69.523,40.872 69.523,41.513 69.661,41.651 70.872,41.651 71.022,41.501 71.022,40.185 71.124,40.083 71.256,40.083 71.368,40.195 71.368,41.332 71.512,41.476 73.31,41.476 73.464,41.322 73.464,40.013 73.555,39.921 73.711,39.921 73.802,40.012 73.802,40.356 74.026,40.58 80.558,40.58 80.76,40.378 80.76,39.905 v2(81.25,39.415)
DDR_CA5_B: U1.E23 U2.P11 | length 15.5
  Top Layer w0.09: U1.E23@67.375,45.825 67.377,45.823 67.852,45.823 v3(67.855,45.82) ; v2@81.268,43.3 81.652,42.915 U2.P11@81.66,42.915
  Bottom Layer w0.09: v3(67.855,45.82) 73.832,45.82 75.853,43.799 79.828,43.799 80.084,43.543 80.572,43.543 80.821,43.294 81.239,43.294 v2(81.26,43.315)
DDR_CKE0_A: U1.U21 U2.J4 | length 23.4
  Top Layer w0.09: U1.U21@66.375,39.825 66.375,39.4 v3@66.875,38.9 ; v2(86.835,39.325) 86.894,39.384 86.979,39.384 U2.J4@87.26,39.665
  Bottom Layer w0.09: v3(66.875,38.91) 67.114,38.671 67.602,38.671 67.813,38.46 68.938,38.46 70.028,37.37 81.462,37.37 81.862,36.97 82.228,36.97 82.628,37.37 84.049,37.37 84.328,37.649 84.575,37.649 85.921,38.995 86.514,38.995 v2@86.835,39.316
DDR_CKE0_B: U1.L23 U2.P4 | length 21.3
  Top Layer w0.09: U1.L23@67.375,42.825 v3(67.95,42.825) ; v2(86.86,42.665) 87.079,42.884 87.229,42.884 U2.P4@87.26,42.915
  Bottom Layer w0.09: v3(67.95,42.825) 73.854,42.825 74.554,42.125 79.394,42.125 79.91,41.609 80.615,41.609 80.773,41.45 82.019,41.45 82.304,41.165 84.14,41.165 85.633,42.659 v2@86.854,42.659
DDR_CLK_A_N: U1.T24 U2.J9 | length 22.6
  Top Layer w0.09: U1.T24@67.875,40.325 67.9,40.3 67.9,39.925 v3@67.925,39.9 ; U2.J9@83.26,39.665 83.3,39.625 83.428,39.625 v2@83.659,39.394
  Bottom Layer w0.09: v3@67.928,39.907 67.928,39.6 68.047,39.481 69.935,39.481 71.215,38.2 74.88,38.2 75.033,38.353 75.033,39.164 75.289,39.42 75.682,39.42 75.924,39.177 75.924,38.291 76.015,38.2 78.207,38.2 78.289,38.282 78.289,38.92 78.691,39.321 79.203,39.321 79.577,38.946 79.577,38.307 79.684,38.2 83.547,38.2 83.914,38.566 83.914,39.14 v2@83.659,39.395
  other v2: 83.66,39.39
  other v3: 67.925,39.91
DDR_CLK_A_P: U1.U23 U2.J8 | length 23.2
  Top Layer w0.09: U1.U23@67.375,39.825 67.4,39.8 67.4,39.425 v3@67.425,39.4 ; U2.J8@84.06,39.665 84.1,39.625 84.217,39.625 84.448,39.394 v2@84.459,39.394
  Bottom Layer w0.09: v3@67.426,39.409 67.765,39.409 67.944,39.231 69.831,39.231 71.112,37.95 74.983,37.95 75.283,38.25 75.283,39.06 75.392,39.17 75.578,39.17 75.674,39.074 75.674,38.187 75.912,37.95 78.311,37.95 78.539,38.179 78.539,38.816 78.794,39.071 79.099,39.071 79.327,38.843 79.327,38.203 79.58,37.95 83.651,37.95 84.164,38.463 84.164,39.101 v2@84.458,39.395
  other v2: 84.46,39.39
  other v3: 67.425,39.41
DDR_CLK_B_N: U1.H24 U2.P9 | length 19.2
  Top Layer w0.09: U1.H24@67.875,44.325 v3(67.875,44.74) v3@67.875,44.825 ; U2.P9@83.26,42.915 83.574,42.601 v2(83.574,42.59)
  Bottom Layer w0.09: v3@67.883,44.746 67.85,44.713 67.85,44.446 68.026,44.271 73.388,44.271 74.784,42.874 79.408,42.874 80.134,42.149 80.838,42.149 80.997,41.99 82.421,41.99 82.706,41.705 83.489,41.705 83.848,42.064 83.848,42.315 v2(83.574,42.59)
DDR_CLK_B_P: U1.J23 U2.P8 | length 19.7
  Top Layer w0.09: U1.J23@67.375,43.825 v3(67.375,44.24) ; U2.P8@84.06,42.915 84.06,42.909 v2@84.374,42.595
  Bottom Layer w0.09: v3(67.375,44.24) 67.421,44.286 67.657,44.286 67.923,44.021 73.284,44.021 74.68,42.624 79.304,42.624 80.03,41.899 80.735,41.899 80.893,41.74 82.318,41.74 82.603,41.455 83.592,41.455 84.098,41.96 84.098,42.319 v2@84.373,42.595
  other v2: 84.374,42.59
DDR_CS0_A: U1.Y24 U2.H4 | length 21.2
  Top Layer w0.09: U1.Y24@67.875,38.325 67.875,38.302 67.969,38.208 67.969,37.925 v3@67.972,37.922 ; v2(86.835,38.74) 86.893,38.799 87.002,38.799 87.217,39.015 U2.H4@87.26,39.015
  Bottom Layer w0.09: v3(67.97,37.92) 68.746,37.92 69.768,36.898 79.991,36.898 80.208,36.68 82.755,36.68 83.004,36.929 84.019,36.929 84.449,37.359 85.448,37.359 v2@86.834,38.745
DDR_CS0_B: U1.G23 U2.R4 | length 22
  Top Layer w0.09: U1.G23@67.375,44.825 v3(67.375,45.325) ; v2(86.86,43.94) 86.885,43.94 U2.R4@87.26,43.565
  Bottom Layer w0.09: v3(67.375,45.325) 67.425,45.375 73.867,45.375 75.733,43.509 79.607,43.509 79.933,43.184 80.502,43.184 80.715,42.97 81.79,42.97 82.455,43.635 84.251,43.635 84.556,43.94 v2(86.86,43.94)
DDR_DQ0_A: U1.AB26 U2.B2 | length 28.6
  Top Layer w0.09: U1.AB26@68.875,37.325 68.901,37.351 69.047,37.351 69.271,37.575 69.643,37.575 70.245,36.973 70.245,36.216 71.087,35.374 71.222,35.374 71.329,35.481 71.433,35.481 71.516,35.398 71.516,34.945 72.9,33.561 73.102,33.561 73.182,33.482 73.182,33.279 73.261,33.2 73.413,33.2 73.775,33.561 73.886,33.561 73.956,33.492 73.956,33.304 73.623,32.971 73.623,32.838 73.718,32.743 73.877,32.743 73.956,32.664 73.956,32.505 ; 73.956,32.505 75.841,30.62 84.663,30.62 84.748,30.705 84.917,30.705 85.001,30.62 85.834,30.62 86.48,31.266 86.48,31.447 86.554,31.521 86.735,31.521 87.343,32.129 87.343,32.392 87.415,32.464 87.678,32.464 88.095,32.881 88.187,32.881 89.159,33.853 89.159,33.975 89.016,34.117 89.016,34.218 89.159,34.361 89.159,34.609 88.878,34.89 88.878,35.075 U2.B2@88.859,35.094
DDR_DQ0_B: U1.F25 U2.AA2 | length 27.9
  Top Layer w0.09: U1.F25@68.375,45.325 68.389,45.339 68.535,45.339 68.771,45.575 68.979,45.575 68.983,45.579 68.992,45.579 69.182,45.769 70.734,45.769 75.355,50.39 77.311,50.39 77.399,50.301 77.399,49.414 77.47,49.344 77.625,49.344 77.696,49.415 77.696,49.699 77.751,49.754 77.943,49.754 77.996,49.701 77.996,49.416 78.069,49.344 78.198,49.344 78.269,49.414 78.269,50.298 78.361,50.39 86.882,50.39 87.285,49.987 87.285,49.888 87.106,49.71 87.106,49.524 87.419,49.21 87.854,49.21 87.957,49.313 88.065,49.313 89.154,48.224 89.154,47.723 88.875,47.444 U2.AA2@88.859,47.444
DDR_DQ1_A: U1.AC26 U2.C2 | length 28.7
  Top Layer w0.09: U1.AC26@68.877,36.829 68.897,36.829 69.143,37.075 69.479,37.075 69.665,36.889 69.665,35.976 75.601,30.04 86.074,30.04 89.813,33.779 89.813,34.215 89.945,34.347 89.945,34.585 89.761,34.769 89.567,34.769 89.364,34.972 89.364,35.306 88.905,35.765 U2.C2@88.86,35.765
DDR_DQ1_B: U1.E26 U2.Y2 | length 27.1
  Top Layer w0.09: U1.E26@68.877,45.829 68.9,45.852 68.996,45.852 69.103,45.959 70.514,45.959 75.235,50.68 77.637,50.68 77.689,50.627 77.689,50.097 77.742,50.044 77.926,50.044 77.979,50.097 77.979,50.614 78.045,50.68 87.002,50.68 87.695,49.987 87.695,49.889 87.518,49.712 87.518,49.577 87.596,49.5 87.734,49.5 87.96,49.726 88.062,49.726 89.364,48.424 89.364,47.29 88.868,46.794 U2.Y2@88.859,46.794
DDR_DQ2_A: U1.AB27 U2.E2 | length 28.9
  Top Layer w0.09: U1.AB27@69.375,37.325 69.571,37.325 69.955,36.941 69.955,36.096 75.721,30.33 85.954,30.33 89.564,33.94 89.564,34.158 89.349,34.373 89.349,34.687 89.154,34.882 89.154,35.237 88.991,35.4 88.786,35.4 88.564,35.622 88.564,36.769 U2.E2@88.86,37.065
DDR_DQ2_B: U1.F24 U2.V2 | length 29
  Top Layer w0.09: U1.F24@67.875,45.325 68.125,45.575 68.479,45.575 68.625,45.721 68.625,45.931 68.843,46.149 70.294,46.149 75.115,50.97 87.122,50.97 88.076,50.016 88.182,50.016 89.945,48.253 89.945,46.697 89.717,46.469 89.542,46.469 89.187,46.114 89.187,45.804 88.877,45.494 U2.V2@88.859,45.494
DDR_DQ3_A: U1.AC27 U2.F2 | length 30.5
  Top Layer w0.09: U1.AC27@69.375,36.825 69.375,35.856 75.481,29.75 86.194,29.75 90.135,33.691 90.135,35.043 89.738,35.44 89.582,35.44 89.364,35.658 89.364,37.233 88.882,37.715 U2.F2@88.86,37.715
DDR_DQ3_B: U1.E25 U2.U2 | length 29.8
  Top Layer w0.09: U1.E25@68.375,45.825 68.402,45.852 68.402,45.989 68.562,46.149 68.575,46.149 68.765,46.339 70.074,46.339 74.995,51.26 87.242,51.26 90.317,48.185 90.317,45.697 89.814,45.194 89.434,45.194 89.159,44.919 88.934,44.919 U2.U2@88.859,44.844
DDR_DQ4_A: U1.W25 U2.F4 | length 29.9
  Top Layer w0.09: U1.W25@68.377,38.829 68.623,39.075 70.717,39.075 72.632,37.16 73.793,37.16 74.916,36.037 74.916,35.923 74.835,35.842 74.699,35.842 74.088,36.454 73.97,36.454 73.882,36.366 73.882,36.249 74.58,35.551 75.401,35.551 78.342,32.61 79.496,32.61 79.557,32.55 82.962,32.55 83.022,32.61 83.838,32.61 84.956,33.728 85.488,33.728 85.578,33.818 85.578,33.949 85.251,34.276 85.251,34.598 85.548,34.895 85.548,35.03 85.309,35.269 85.309,35.744 85.409,35.844 85.409,35.988 85.309,36.088 85.309,36.579 85.409,36.679 85.409,36.791 85.129,37.071 85.129,37.261 85.267,37.399 86.546,37.399 86.783,37.162 86.93,37.162 87.255,37.487 U2.F4@87.255,37.71
DDR_DQ4_B: U1.J25 U2.U4 | length 28.2
  Top Layer w0.09: U1.J25@68.37,43.837 68.71,44.177 71.957,44.177 72.305,44.525 72.536,44.525 72.664,44.653 72.664,44.884 75.234,47.454 76.021,47.454 77.447,46.028 77.89,46.028 78.138,45.78 78.821,45.78 79.158,46.117 79.158,46.196 79.557,46.596 79.557,46.81 80.273,47.527 ; 80.274,47.527 80.274,47.693 80.564,47.982 80.564,48.222 80.742,48.4 80.978,48.4 81.135,48.243 81.385,48.243 81.542,48.4 81.778,48.4 81.946,48.233 82.174,48.233 82.342,48.4 82.578,48.4 82.713,48.266 83.007,48.266 83.142,48.4 83.378,48.4 83.524,48.254 83.796,48.254 83.942,48.4 84.767,48.4 84.86,48.307 84.86,47.879 84.656,47.674 84.656,47.525 84.737,47.445 85.004,47.445 85.076,47.373 85.076,47.105 85.724,46.457 85.724,46.142 85.897,45.969 86.184,45.969 86.281,45.871 86.281,45.761 86.197,45.677 85.962,45.677 85.854,45.569 85.854,45.362 85.968,45.247 86.183,45.247 86.258,45.172 86.258,45.067 86.121,44.929 85.936,44.929 85.854,44.847 85.854,44.724 85.948,44.63 86.237,44.63 86.339,44.528 87.147,44.528 87.261,44.641 U2.U4@87.26,44.865
DDR_DQ5_A: U1.W27 U2.E4 | length 29.1
  Top Layer w0.09: U1.W27@69.377,38.829 69.391,38.815 70.567,38.815 72.512,36.87 73.673,36.87 73.773,36.77 73.773,36.667 73.683,36.577 73.207,36.577 73.121,36.491 73.121,36.304 73.196,36.229 73.492,36.229 74.22,35.501 74.222,35.5 74.222,35.345 74.305,35.261 75.28,35.261 75.892,34.65 ; 75.892,34.65 76.055,34.488 76.055,34.351 75.765,34.061 75.765,33.956 75.864,33.857 75.972,33.857 76.263,34.148 76.394,34.148 77.891,32.651 77.891,32.428 77.999,32.32 83.959,32.32 85.076,33.438 85.83,33.438 86.109,33.718 86.109,33.842 85.654,34.297 85.654,34.591 86.003,34.94 86.003,35.041 85.599,35.445 85.599,35.624 85.722,35.747 85.722,36.085 85.599,36.208 85.599,36.457 85.759,36.617 86.055,36.617 86.218,36.78 86.544,36.78 86.791,36.533 86.893,36.533 87.065,36.705 87.645,36.705 87.728,36.787 87.728,36.944 87.646,37.025 87.3,37.025 U2.E4@87.26,37.065
DDR_DQ5_B: U1.H25 U2.V4 | length 27.7
  Top Layer w0.09: U1.H25@68.375,44.325 68.417,44.367 71.737,44.367 75.114,47.744 76.141,47.744 77.568,46.318 78.01,46.318 78.258,46.07 78.701,46.07 78.868,46.237 78.868,46.316 79.267,46.716 79.267,46.954 79.983,47.67 79.984,47.828 80.274,48.117 80.274,48.577 80.387,48.69 81.098,48.69 81.223,48.565 81.297,48.565 81.422,48.69 81.898,48.69 82.022,48.566 82.097,48.566 82.221,48.69 82.698,48.69 82.823,48.565 82.897,48.565 83.022,48.69 83.498,48.69 83.583,48.605 83.623,48.565 83.697,48.565 83.822,48.69 85,48.69 85.261,48.429 85.5,48.429 85.559,48.37 85.559,48.135 85.506,48.082 85.228,48.082 85.15,48.004 85.15,47.804 85.203,47.751 85.561,47.751 85.645,47.667 85.645,47.478 85.537,47.37 85.437,47.37 85.366,47.3 85.366,47.225 85.688,46.904 86.046,46.904 86.274,47.132 86.558,47.132 86.837,46.853 86.837,46.715 87.061,46.491 87.654,46.491 87.742,46.404 87.742,45.81 87.662,45.73 87.506,45.73 87.27,45.494 U2.V4@87.259,45.494
DDR_DQ6_A: U1.W26 U2.C4 | length 29.1
  Top Layer w0.09: U1.W26@68.875,38.825 69.125,38.575 69.479,38.575 69.529,38.625 70.347,38.625 72.392,36.58 72.738,36.58 72.831,36.487 72.831,36.141 73.032,35.939 73.372,35.939 73.897,35.415 73.897,35.054 73.979,34.971 75.16,34.971 75.652,34.479 75.652,34.359 75.366,34.072 75.366,33.945 75.863,33.448 75.973,33.448 76.271,33.746 76.386,33.746 77.601,32.531 77.601,32.389 77.532,32.319 77.402,32.319 76.38,33.341 76.276,33.341 76.18,33.245 76.18,33.13 77.28,32.03 84.079,32.03 85.196,33.148 85.952,33.148 86.441,33.637 86.44,33.638 86.44,34.042 86.745,34.347 86.745,34.446 86.747,34.448 86.747,34.581 86.605,34.723 86.605,34.857 86.836,35.088 86.836,35.254 86.745,35.345 86.745,35.452 86.835,35.542 87.037,35.542 U2.C4@87.26,35.765
DDR_DQ6_B: U1.G26 U2.Y4 | length 25.9
  Top Layer w0.09: U1.G26@68.877,44.829 69.133,44.573 71.533,44.573 74.994,48.034 75.629,48.034 75.7,48.106 75.7,48.718 75.828,48.846 75.923,48.846 75.989,48.779 75.989,48.104 76.059,48.034 76.261,48.034 77.687,46.608 77.972,46.608 78.131,46.608 78.378,46.36 78.502,46.36 78.596,46.455 78.596,46.553 78.391,46.759 78.391,46.862 78.466,46.938 78.634,46.938 78.807,46.765 78.906,46.765 78.977,46.836 78.977,47.074 79.694,47.792 79.694,47.948 79.984,48.238 79.984,48.899 80.065,48.98 85.224,48.98 85.485,48.719 85.811,48.719 85.864,48.666 85.864,47.944 85.932,47.876 86.13,47.876 86.247,47.759 86.577,47.759 86.754,47.582 86.754,47.248 87.208,46.794 U2.Y4@87.259,46.794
